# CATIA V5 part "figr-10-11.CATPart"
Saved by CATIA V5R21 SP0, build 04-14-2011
Part number: Part1
Bounding box of the stored display mesh (mm): x -100 to 0, y -100 to 90, z 0 to 33.63
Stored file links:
  D:\CATIA V5R21 E-RESOURCES\CATIA-V5R21\catia-v5r21-prt\c10-catia-v5r20-prt\c10-catia-v5r21-figr-10-11.CATPart
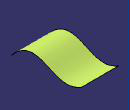
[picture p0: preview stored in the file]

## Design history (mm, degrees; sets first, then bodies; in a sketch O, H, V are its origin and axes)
Set1
  Sketch1 on face of yz-plane, origin (0, 0, 0), H (0, 0, -1), V (0, 1, 0)
    spline S1 through (0, -100) (-30, -20) (-10, 30) (-20, 90)
  Extrude1: Element1 Sketch1, Lim1 0, Lim2 100, Direction face of yz-plane
Body1 (main body)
